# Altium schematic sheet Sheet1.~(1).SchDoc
size A4; SheetNumber: 2; SheetTotal: 2
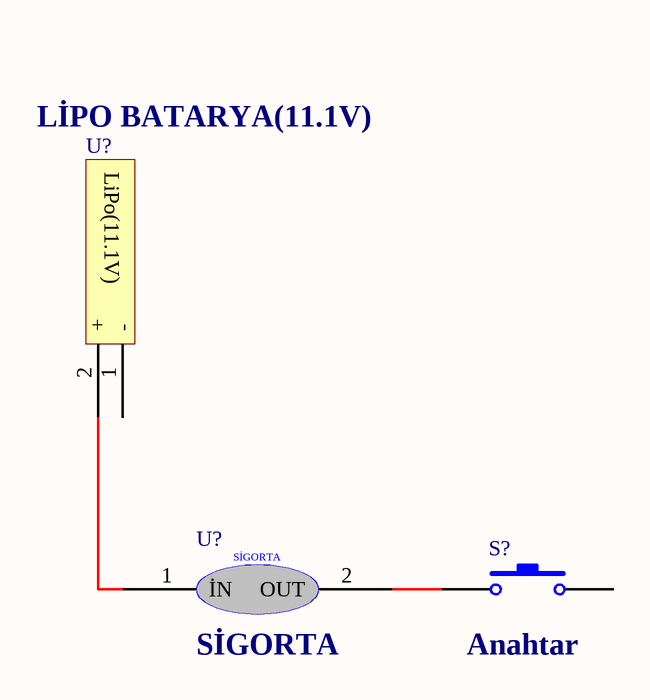
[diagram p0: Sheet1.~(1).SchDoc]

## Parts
(Parts that share a designator on the sheet are numbered #1, #2 ... from top to bottom, then left to right.)
S?  Anahtar  [SPST-2]
U?#1  LİPO BATARYA(11.1V)
U?#2  SİGORTA

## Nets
NetS?_1: S?.1 U?#2.2(OUT)
NetU?#1_2: U?#1.2(+) U?#2.1(İN)

Not connected (* = marked no-connect by the designer): S? 2; U?#1 1(-)

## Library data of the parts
S? = SW-PB: Switch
